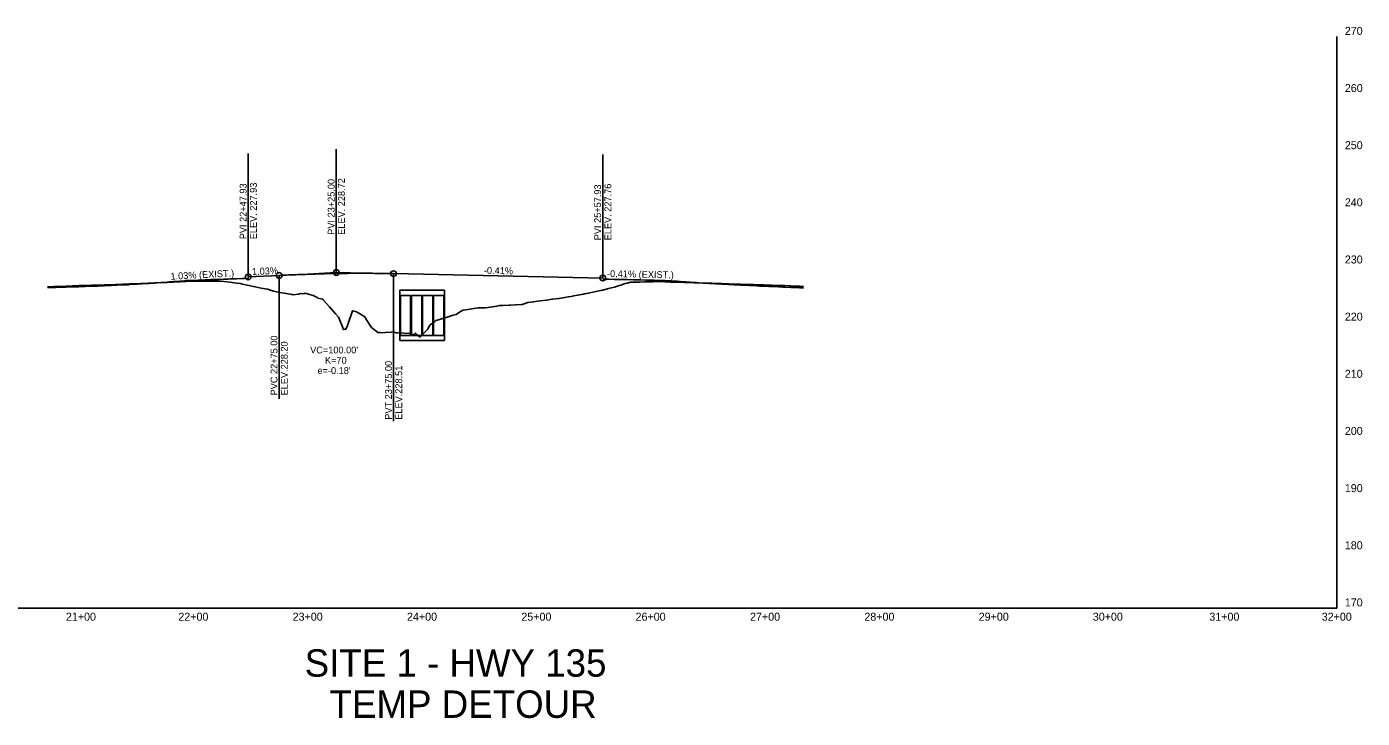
# Model space of a CAD drawing. Extents: x 1805251 to 1808760, y 516965 to 518393.
# Drawn here: x 1807592 to 1808760, y 517446 to 518051 of the extents above; entities that cross this region are included whole.
import ezdxf

# ---------------------------------------------------------------- set-up
doc = ezdxf.new("R2010")
doc.units = 0
for name, color, linetype in [('Default', 7, 'Continuous'), ('R_Axis', 7, 'Continuous'), ('R_Axis Annot', 7, 'Continuous'), ('R_Concrete', 7, 'Continuous'), ('R_Exist Surface', 7, 'Continuous'), ('R_Horz Alg Annot', 7, 'Continuous'), ('R_Vert Alg', 7, 'Continuous'), ('R_Vert Alg Annot', 7, 'Continuous')]:
    doc.layers.add(name, color=color, linetype=linetype)

msp = doc.modelspace()

# ---------------------------------------------------------------- linework, layer by layer
at = {"layer": 'R_Axis'}
for p, q in [((1808737.6, 517542.2), (1808737.6, 518042.2)), ((1807237.6, 517542.2), (1808737.6, 517542.2))]:
    msp.add_line(p, q, dxfattribs=at)
at = {"layer": 'R_Concrete'}
for p, q in [((1807918, 517820.3), (1807918, 517776.2)), ((1807918, 517820.3), (1807957.2, 517820.3)), ((1807918.6, 517815.8), (1807927.6, 517815.8)), ((1807918.6, 517815.8), (1807918.6, 517780.8)), ((1807927.6, 517815.8), (1807927.6, 517780.8)), ((1807928.3, 517815.8), (1807928.3, 517780.8)), ((1807928.3, 517815.8), (1807937.3, 517815.8)), ((1807937.3, 517815.8), (1807937.3, 517780.8)), ((1807938, 517815.8), (1807938, 517780.8)), ((1807938, 517815.8), (1807947, 517815.8)), ((1807947, 517815.8), (1807947, 517780.8)), ((1807947.6, 517815.8), (1807947.6, 517780.8)), ((1807947.6, 517815.8), (1807956.6, 517815.8)), ((1807956.6, 517815.8), (1807956.6, 517780.8)), ((1807957.2, 517820.3), (1807957.2, 517776.2)), ((1807927.6, 517780.8), (1807918.6, 517780.8)), ((1807937.3, 517780.8), (1807928.3, 517780.8)), ((1807947, 517780.8), (1807938, 517780.8)), ((1807956.6, 517780.8), (1807947.6, 517780.8)), ((1807957.2, 517776.2), (1807918, 517776.2))]:
    msp.add_line(p, q, dxfattribs=at)
at = {"layer": 'R_Exist Surface'}
for points in [[(1807609.9, 517822.6), (1807615.4, 517822.8), (1807617, 517822.8), (1807617.8, 517822.9), (1807620.9, 517822.9), (1807626.4, 517823.1), (1807631.9, 517823.3), (1807637.4, 517823.4), (1807640, 517823.5), (1807641.3, 517823.6), (1807642.8, 517823.6), (1807642.9, 517823.6), (1807648.5, 517823.8), (1807654, 517824), (1807659.5, 517824.2), (1807663, 517824.3), (1807665, 517824.4), (1807665.8, 517824.4), (1807670.5, 517824.6), (1807676, 517824.9), (1807680.4, 517825.1), (1807681.5, 517825.2), (1807687, 517825.6), (1807688.8, 517825.7), (1807692.5, 517825.9), (1807698.1, 517826.2), (1807698.8, 517826.3), (1807703.6, 517826.6), (1807709.1, 517827), (1807711.8, 517827.2), (1807714.6, 517827.5), (1807716.4, 517827.6), (1807720.1, 517827.9), (1807725.6, 517828.3), (1807730.1, 517828.6), (1807731.1, 517828.7), (1807734.4, 517828.8), (1807735.8, 517828.9), (1807736.6, 517828.9), (1807742.1, 517829.1), (1807747.7, 517829.3), (1807752.1, 517829.5), (1807753.2, 517829.6), (1807758.7, 517829.8), (1807759.5, 517829.8), (1807764.2, 517830), (1807767.9, 517830.1), (1807769.7, 517830.2), (1807775.2, 517830.4), (1807780.6, 517830.6), (1807782.4, 517830.7), (1807786.1, 517830.9)], [(1807609.9, 517823.4), (1807615.4, 517823.6), (1807616, 517823.6), (1807616.7, 517823.6), (1807620.9, 517823.7), (1807626.4, 517823.9), (1807629.2, 517824), (1807629.4, 517824), (1807631.9, 517824.1), (1807633.7, 517824.2), (1807637.4, 517824.3), (1807641.6, 517824.4), (1807641.9, 517824.4), (1807642.9, 517824.5), (1807648.5, 517824.6), (1807653.6, 517824.8), (1807654, 517824.8), (1807654.6, 517824.8), (1807659.5, 517824.9), (1807665, 517825.1), (1807665.4, 517825.1), (1807667.3, 517825.1), (1807669.7, 517825.3), (1807670.5, 517825.3), (1807676, 517825.5), (1807681.5, 517825.8), (1807687, 517826), (1807687.1, 517826), (1807691.9, 517826.2), (1807692.5, 517826.3), (1807698.1, 517826.5), (1807698.5, 517826.5), (1807703.6, 517826.7), (1807709.1, 517827), (1807710.1, 517827), (1807714.6, 517827.2), (1807719.5, 517827.4), (1807720.1, 517827.4), (1807724.7, 517827.6), (1807725.6, 517827.6), (1807731.1, 517827.9), (1807736.6, 517828.1), (1807738, 517828.2), (1807741.3, 517828.2), (1807742.1, 517828.2), (1807747.7, 517828.2), (1807753.2, 517828.3), (1807757.2, 517828.3), (1807758.7, 517828.3), (1807761.3, 517828.3), (1807761.8, 517828.3), (1807764.2, 517828), (1807769.7, 517827.3), (1807775.2, 517826.6), (1807778.1, 517826.2), (1807778.6, 517826.2), (1807780.6, 517825.7), (1807786.1, 517824.5), (1807791.5, 517823.3), (1807796.9, 517822.2), (1807802, 517821.2), (1807802.3, 517821.1), (1807807.7, 517819.6), (1807809.2, 517819.2), (1807813.2, 517818.4), (1807818.6, 517817.5), (1807824, 517816.5), (1807824.7, 517816.4), (1807829.4, 517817), (1807831.7, 517817.4), (1807832.6, 517817.2), (1807834.8, 517817.5), (1807835.4, 517817.6), (1807838.4, 517816.8), (1807840.3, 517816.3), (1807842.3, 517815.7), (1807845.7, 517813.8), (1807846.4, 517813.5), (1807849.2, 517812.9), (1807850.7, 517812.4), (1807851.1, 517811.9), (1807856.5, 517805.7), (1807861.9, 517799.6), (1807864.6, 517796.7), (1807867.4, 517789.7), (1807868.9, 517785.9), (1807869.6, 517786.1), (1807870.6, 517785.9), (1807872.3, 517789.1), (1807872.8, 517790.4), (1807876.8, 517802.4), (1807878.2, 517802), (1807880.3, 517801.4), (1807883.6, 517799.4), (1807887.4, 517797.1), (1807889.1, 517794.5), (1807893.5, 517787.7), (1807894.5, 517786.9), (1807898.9, 517783.4), (1807899.9, 517783.3), (1807900.9, 517783.2), (1807903.4, 517783.1), (1807905.3, 517783.2), (1807910.7, 517783.7), (1807911.9, 517783.9), (1807915.1, 517783.1), (1807916.2, 517783), (1807921.6, 517782.7), (1807927, 517782.5), (1807927.6, 517782.4), (1807929.7, 517781.1), (1807931.8, 517782.8), (1807932.4, 517782.2), (1807933.3, 517781.3), (1807935.5, 517779.3), (1807937.8, 517781.6), (1807938.1, 517781.9), (1807938.9, 517782.5), (1807942.2, 517786), (1807943.3, 517787.7), (1807944.7, 517790), (1807948.7, 517793), (1807949.7, 517793.8), (1807954.1, 517795.1), (1807957.5, 517796.1), (1807959.5, 517796.7), (1807964.9, 517798.4), (1807967.5, 517799.1), (1807970.4, 517801.1), (1807973.1, 517802.9), (1807975.8, 517803.2), (1807981.2, 517804), (1807986.6, 517804.8), (1807986.7, 517804.8), (1807992.1, 517804.8), (1807993.1, 517804.9), (1807997.5, 517805.5), (1808002.9, 517806.5), (1808005.2, 517806.9), (1808008.3, 517806.9), (1808013.7, 517807.1), (1808014.7, 517807.1), (1808019.2, 517807.4), (1808024.6, 517807.7), (1808025, 517807.8), (1808030, 517809.5), (1808030, 517809.5), (1808035.4, 517810.2), (1808038.6, 517810.7), (1808040.8, 517811), (1808046.3, 517811.7), (1808051.2, 517812.4), (1808051.7, 517812.5), (1808057.1, 517813.2), (1808057.6, 517813.2), (1808062.5, 517814), (1808065.3, 517814.5), (1808067.9, 517814.9), (1808070.3, 517815.3), (1808073.4, 517815.9), (1808078.8, 517817), (1808079.5, 517817.1), (1808083, 517817.7), (1808084.2, 517818), (1808089.6, 517819.2), (1808093.8, 517820.2), (1808095, 517820.4), (1808095.6, 517820.5), (1808100.5, 517821.7), (1808105.9, 517823.1), (1808107.7, 517823.6), (1808108, 517823.7), (1808108.3, 517823.8), (1808111.4, 517824.8), (1808115.1, 517826.1), (1808116.9, 517826.6), (1808120.3, 517827.4), (1808122.4, 517827.4), (1808123.9, 517827.4), (1808127.9, 517827.5), (1808132.1, 517827.6), (1808133.4, 517827.6), (1808139, 517827.7), (1808139.4, 517827.7), (1808143.5, 517827.8), (1808144.5, 517827.8), (1808150, 517827.6), (1808154.7, 517827.5), (1808155.5, 517827.5), (1808157.7, 517827.4), (1808161, 517827.3), (1808166.5, 517827.1), (1808170, 517827), (1808172, 517827), (1808175.5, 517826.9), (1808177.5, 517826.8), (1808183, 517826.6), (1808183.2, 517826.6), (1808188.6, 517826.4), (1808191, 517826.4), (1808194.1, 517826.3), (1808196.5, 517826.2), (1808199.6, 517826.1), (1808205.1, 517825.9), (1808206.1, 517825.9), (1808209.7, 517825.7), (1808210.6, 517825.7), (1808216.1, 517825.5), (1808220.9, 517825.4), (1808221.6, 517825.4), (1808223, 517825.3), (1808227.1, 517825.2), (1808232.6, 517825), (1808236.9, 517824.9), (1808238.2, 517824.8), (1808238.2, 517824.8), (1808243.7, 517824.6), (1808249.2, 517824.5), (1808252.7, 517824.3), (1808252.9, 517824.3), (1808254.7, 517824.3), (1808258.8, 517824.1), (1808260.2, 517824.1), (1808265.7, 517823.8), (1808267.5, 517823.8), (1808267.7, 517823.8), (1808267.8, 517823.8), (1808271.2, 517823.6)], [(1808095.6, 517830), (1808096.1, 517830), (1808096.1, 517830), (1808096.1, 517830), (1808100.5, 517829.9), (1808105.9, 517829.8), (1808110.3, 517829.7), (1808111.4, 517829.7), (1808115.9, 517829.6), (1808116.9, 517829.6), (1808122.4, 517829.4), (1808125.5, 517829.4), (1808127.9, 517829.3), (1808133.4, 517829.1), (1808136.3, 517829.1), (1808139, 517829), (1808140.7, 517829), (1808144.5, 517828.8), (1808150, 517828.7), (1808155.5, 517828.5), (1808155.7, 517828.5), (1808155.7, 517828.5), (1808155.7, 517828.5), (1808161, 517828.1), (1808166.5, 517827.7), (1808168.2, 517827.6), (1808171, 517827.4), (1808172, 517827.3), (1808177.5, 517827), (1808179.7, 517826.8), (1808183, 517826.6), (1808184.3, 517826.6), (1808188.6, 517826.3), (1808191.2, 517826.1), (1808194.1, 517826), (1808197.6, 517825.8), (1808199.6, 517825.7), (1808202.9, 517825.5), (1808205.1, 517825.4), (1808210.6, 517825.1), (1808210.8, 517825.1), (1808214.8, 517824.9), (1808216.1, 517824.8), (1808221.6, 517824.6), (1808224, 517824.4), (1808227.1, 517824.3), (1808227.3, 517824.3), (1808232.6, 517824), (1808238.2, 517823.8), (1808238.6, 517823.8), (1808241, 517823.7), (1808243.7, 517823.5), (1808249.2, 517823.3), (1808253.2, 517823.1), (1808254.7, 517823.1), (1808254.9, 517823.1), (1808260.2, 517822.8), (1808265.7, 517822.6), (1808267.7, 517822.5), (1808271.2, 517822.4)]]:
    msp.add_lwpolyline(points, dxfattribs=at)
at = {"layer": 'R_Vert Alg'}
for p, q in [((1807785.6, 517831.9), (1807812.6, 517833.3)), ((1807912.6, 517834.8), (1808095.6, 517831))]:
    msp.add_line(p, q, dxfattribs=at)
msp.add_lwpolyline([(1807812.6, 517833.3), (1807814.7, 517833.4), (1807816.8, 517833.5), (1807818.9, 517833.6), (1807821, 517833.7), (1807823, 517833.8), (1807825.1, 517833.8), (1807827.2, 517833.9), (1807829.3, 517834), (1807831.4, 517834.1), (1807833.5, 517834.2), (1807835.5, 517834.2), (1807837.6, 517834.3), (1807839.7, 517834.4), (1807841.8, 517834.4), (1807843.9, 517834.5), (1807846, 517834.6), (1807848, 517834.6), (1807850.1, 517834.7), (1807852.2, 517834.7), (1807854.3, 517834.8), (1807856.4, 517834.8), (1807858.5, 517834.9), (1807860.5, 517834.9), (1807864.7, 517835), (1807866.8, 517835), (1807868.9, 517835), (1807871, 517835), (1807873, 517835), (1807875.1, 517835.1), (1807877.2, 517835.1), (1807879.3, 517835.1), (1807881.4, 517835.1), (1807883.5, 517835.1), (1807885.5, 517835.1), (1807887.6, 517835.1), (1807889.7, 517835.1), (1807891.8, 517835.1), (1807893.9, 517835.1), (1807896, 517835), (1807898, 517835), (1807900.1, 517835), (1807902.2, 517835), (1807904.3, 517834.9), (1807906.4, 517834.9), (1807908.5, 517834.9), (1807910.5, 517834.8), (1807912.6, 517834.8)], dxfattribs=at)
at = {"layer": 'R_Vert Alg Annot'}
for p, q in [((1807862.6, 517865.8), (1807862.6, 517943.8)), ((1807785.6, 517861.9), (1807785.6, 517939.9)), ((1808095.6, 517861), (1808095.6, 517939)), ((1807785.6, 517831.9), (1807785.6, 517861.9)), ((1807862.6, 517835.8), (1807862.6, 517865.8)), ((1808095.6, 517831), (1808095.6, 517861)), ((1807812.6, 517833.3), (1807812.6, 517803.3)), ((1807837.6, 517834.5), (1807862.6, 517835.8)), ((1807862.6, 517835.8), (1807887.6, 517835.3)), ((1807912.6, 517834.8), (1807912.6, 517804.8)), ((1807812.6, 517803.3), (1807812.6, 517725.3)), ((1807912.6, 517804.8), (1807912.6, 517705.9))]:
    msp.add_line(p, q, dxfattribs=at)
for centre in [(1807862.6, 517835.8), (1807912.6, 517834.8), (1807785.6, 517831.9), (1807812.6, 517833.3), (1808095.6, 517831)]:
    msp.add_circle(centre, 2.5, dxfattribs=at)

# ---------------------------------------------------------------- texts
at = {"layer": 'Default'}
for s, p in [('SITE 1 - HWY 135', (1807834.9, 517482.2)), ('TEMP DETOUR', (1807856.7, 517446.2))]:
    msp.add_text(s, height=24, dxfattribs=at).set_placement(p)
at = {"layer": 'R_Axis Annot'}
for s, p in [('270', (1808744.6, 518043.7)), ('270', (1808744.6, 518043.7)), ('260', (1808744.6, 517993.7)), ('250', (1808744.6, 517943.7)), ('240', (1808744.6, 517893.7)), ('230', (1808744.6, 517843.7)), ('220', (1808744.6, 517793.7)), ('210', (1808744.6, 517743.7)), ('200', (1808744.6, 517693.7)), ('190', (1808744.6, 517643.7)), ('180', (1808744.6, 517593.7)), ('170', (1808744.6, 517543.7)), ('21+00', (1807626.1, 517531.2)), ('22+00', (1807724.4, 517531.2)), ('23+00', (1807824.4, 517531.2)), ('24+00', (1807924.4, 517531.2)), ('25+00', (1808024.4, 517531.2)), ('26+00', (1808124.3, 517531.2)), ('27+00', (1808224.4, 517531.2)), ('28+00', (1808324.4, 517531.2)), ('29+00', (1808424.4, 517531.2)), ('30+00', (1808524.2, 517531.2)), ('31+00', (1808626.1, 517531.2)), ('32+00', (1808724.4, 517531.2))]:
    msp.add_text(s, height=7, dxfattribs=at).set_placement(p)
at = {"layer": 'R_Horz Alg Annot'}
for s, rotation, p in [('1.03% (EXIST.)', 2.9392, (1807717.7, 517829.5)), ('-0.41% (EXIST.)', 358.8198, (1808099.3, 517831.9))]:
    msp.add_text(s, height=6, rotation=rotation, dxfattribs=at).set_placement(p)
at = {"layer": 'R_Vert Alg Annot'}
for s, rotation, p in [('PVI 22+47.93', 90, (1807784.1, 517864.9)), ('ELEV. 227.93', 90, (1807793.1, 517864.9)), ('PVI 23+25.00', 90, (1807861.1, 517868.8)), ('ELEV. 228.72', 90, (1807870.1, 517868.8)), ('PVI 25+57.93', 90, (1808094.1, 517864)), ('ELEV. 227.76', 90, (1808103.1, 517864)), ('1.03%', 2.944, (1807789, 517833.5)), ('-0.41%', 358.8251, (1807991.6, 517834.7)), ('PVC 22+75.00', 90, (1807811.1, 517728.3)), ('ELEV.228.20', 90, (1807820.1, 517728.3)), ('PVT 23+75.00', 90, (1807911.2, 517707)), ('ELEV.228.51', 90, (1807920.2, 517707))]:
    msp.add_text(s, height=6, rotation=rotation, dxfattribs=at).set_placement(p)
for s, p in [("VC=100.00'", (1807839.7, 517765)), ('K=70', (1807852.7, 517756)), ("e=-0.18'", (1807846.1, 517747))]:
    msp.add_text(s, height=6, dxfattribs=at).set_placement(p)

doc.saveas('drawing.dxf')
